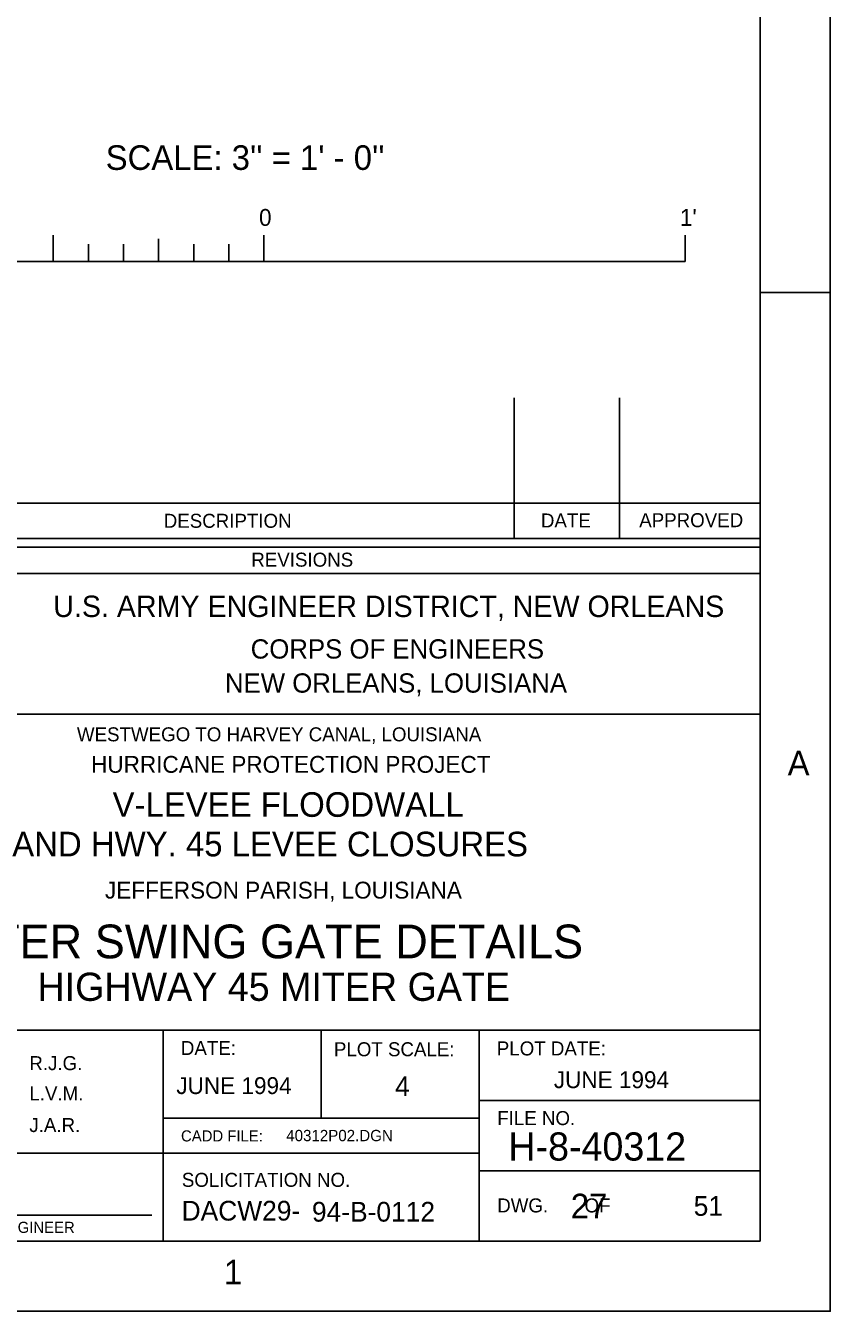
# Model space of a CAD drawing. Extents: x -0.4 to 13.5, y 0 to 9.5.
# Drawn here: x 11.549 to 13.458, y 0.125 to 3.175 of the extents above; entities that cross this region are included whole.
import ezdxf

# ---------------------------------------------------------------- set-up
doc = ezdxf.new("R2010")
doc.units = 0
doc.layers.add('Level 1', color=7, linetype='Continuous')
doc.layers.add('Level 2', color=7, linetype='Continuous')

msp = doc.modelspace()

# ---------------------------------------------------------------- linework, layer by layer
at = {"layer": 'Level 1'}
for p, q in [((11.614, 2.6149), (11.614, 2.6774)), ((11.6974, 2.6149), (11.6974, 2.6566)), ((11.7807, 2.6149), (11.7807, 2.6566)), ((11.864, 2.6149), (11.864, 2.6686)), ((11.9474, 2.6149), (11.9474, 2.6566)), ((12.0307, 2.6149), (12.0307, 2.6566)), ((12.114, 2.6149), (12.114, 2.6774)), ((13.114, 2.6149), (13.114, 2.6774)), ((11.114, 2.6149), (13.114, 2.6149)), ((13.2917, 2.5417), (13.4583, 2.5417)), ((12.7083, 1.9583), (12.7083, 2.2917)), ((12.9583, 1.9583), (12.9583, 2.2917)), ((13.2917, 2.0417), (11.125, 2.0417)), ((13.2917, 1.9583), (11.125, 1.9583)), ((13.2917, 1.9375), (11.125, 1.9375)), ((13.2917, 1.875), (11.125, 1.875)), ((13.2917, 1.5417), (11.125, 1.5417)), ((13.2917, 0.7917), (11.125, 0.7917)), ((11.875, 0.2917), (11.875, 0.7917)), ((12.25, 0.5833), (12.25, 0.7917)), ((12.625, 0.2917), (12.625, 0.7917)), ((13.2917, 0.625), (12.625, 0.625)), ((12.625, 0.5833), (11.875, 0.5833)), ((11.125, 0.5), (11.875, 0.5)), ((12.625, 0.5), (11.875, 0.5)), ((13.2917, 0.4583), (12.625, 0.4583)), ((11.1474, 0.3528), (11.8484, 0.3528))]:
    msp.add_line(p, q, dxfattribs=at)
for points in [[(0.125, 9.4583), (13.4583, 9.4583), (13.4583, 0.125), (0.125, 0.125)], [(0.625, 9.2917), (13.2917, 9.2917), (13.2917, 0.2917), (0.625, 0.2917)]]:
    msp.add_lwpolyline(points, close=True, dxfattribs=at)

# ---------------------------------------------------------------- texts
for s, height, p in [("SCALE: 3'' = 1' - 0''", 0.058332, (11.7385, 2.8325)), ('0', 0.04, (12.1025, 2.6998)), ("1'", 0.04, (13.1014, 2.6998)), ('DESCRIPTION', 0.033208, (11.8763, 1.9835)), ('DATE', 0.03321, (12.7715, 1.9843)), ('APPROVED', 0.03321, (13.0048, 1.985)), ('REVISIONS', 0.03321, (12.0841, 1.8913)), ('U.S. ARMY ENGINEER DISTRICT, NEW ORLEANS', 0.050792, (11.6141, 1.7718)), ('CORPS OF ENGINEERS', 0.045713, (12.0827, 1.6733)), ('NEW ORLEANS, LOUISIANA', 0.045713, (12.0217, 1.5925)), ('A', 0.0584, (13.3571, 1.3961)), ('DATE:', 0.03321, (11.917, 0.7329)), ('PLOT SCALE:', 0.033208, (12.2802, 0.73)), ('PLOT DATE:', 0.03321, (12.6668, 0.7319)), ('FILE NO.', 0.03321, (12.6678, 0.5667)), ('CADD FILE:', 0.02642, (11.9173, 0.5278)), ('SOLICITATION NO.', 0.033208, (11.9193, 0.4202)), ('DACW29-', 0.04679, (11.9187, 0.3402)), ('DWG.       OF', 0.033208, (12.6678, 0.3595)), ('DESIGN ENGINEER', 0.026417, (11.3353, 0.3109)), ('1', 0.0584, (12.0192, 0.1887))]:
    msp.add_text(s, height=height, dxfattribs=at).set_placement(p)
at = {"layer": 'Level 2'}
for s, height, p in [('WESTWEGO TO HARVEY CANAL, LOUISIANA', 0.033208, (11.6702, 1.477)), ('HURRICANE PROTECTION PROJECT', 0.04, (11.7039, 1.4023)), ('V-LEVEE FLOODWALL', 0.058417, (11.7549, 1.2979)), ('AND HWY. 45 LEVEE CLOSURES', 0.058417, (11.5167, 1.2041)), ('JEFFERSON PARISH, LOUISIANA', 0.04, (11.7368, 1.104)), ('MITER SWING GATE DETAILS', 0.08, (11.35, 0.9623)), ('HIGHWAY 45 MITER GATE', 0.066792, (11.5767, 0.8614)), ('R.J.G.', 0.03321, (11.5573, 0.697)), ('JUNE 1994', 0.04, (11.9062, 0.6403)), ('4', 0.0468, (12.4254, 0.6354)), ('JUNE 1994', 0.04, (12.8021, 0.6543)), ('L.V.M.', 0.03321, (11.5573, 0.6252)), ('J.A.R.', 0.03321, (11.5573, 0.5502)), ('40312P02.DGN', 0.026792, (12.1671, 0.5285)), ('H-8-40312', 0.06679, (12.6942, 0.4825)), ('27', 0.05842, (12.8423, 0.3454)), ('51', 0.04679, (13.1341, 0.3515)), ('94-B-0112', 0.04679, (12.228, 0.3377))]:
    msp.add_text(s, height=height, dxfattribs=at).set_placement(p)

doc.saveas('drawing.dxf')
